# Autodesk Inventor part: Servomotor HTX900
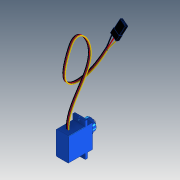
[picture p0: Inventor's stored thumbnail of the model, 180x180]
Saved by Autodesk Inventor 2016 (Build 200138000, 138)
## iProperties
Created: 2016-01
Part Number: Servomotor HTX900
Material: Поликарбонат, дымчатый
Document SubType Name: Modeling
Designer: Evgeny
Density: 1.2 g/cm^3
Appearance: Анодированный — синий
Author: Evgeny
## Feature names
1. Выдавливание1 [Extrusion]
2. Выдавливание2 [Extrusion]
3. Выдавливание3 [Extrusion]
4. Выдавливание4 [Extrusion]
5. Сопряжение1 [Fillet]
6. Выдавливание5 [Extrusion]
7. Выдавливание6 [Extrusion]
8. Сдвиг1
9. Выдавливание7 [Extrusion]
10. Выдавливание8 [Extrusion]
11. Сдвиг2
12. Сопряжение2 [Fillet]
13. Выдавливание9 [Extrusion]
14. Выдавливание10 [Extrusion]
15. Сдвиг3
16. Сдвиг4
17. Выдавливание11 [Extrusion]
## Parameters: d0 = 12 mm, d1 = 23 mm, d2 = 0.5 mm, d3 = 16 mm, d4 = 0, d5 = 12 mm, d6 = 32.5 mm, d7 = 2 mm, d8 = 2 mm, d9 = 1 mm, d10 = 0.5 mm, d11 = 2 mm, d12 = 0, d13 = 27 mm, d14 = 13.5 mm, d15 = 22.5 mm, d16 = 5 mm, d17 = 0, d18 = 12 mm, d19 = 11.5 mm, d20 = 5.25 mm, d21 = 5.5 mm, d22 = 6 mm, d23 = 11.25 mm, d24 = 4 mm, d25 = 0, d26 = 0.25 mm, d27 = 1.5 mm, d28 = 1.5 mm, d29 = 1.5 mm, d30 = 5 mm, d31 = 0.25 mm, d32 = 0.25 mm, d33 = 0, d34 = 4.5 mm, d35 = 1 mm, d36 = 3 mm, d37 = 0, d38 = 1 mm, d39 = 1 mm, d40 = 1 mm, d41 = 2 mm, d42 = 1 mm, d43 = 5 mm, d44 = 0.8 mm, d45 = 0.4 mm, d46 = 0.4 mm, d47 = 0.2 mm, d48 = 0.5 mm, d49 = 0.5 mm, d50 = 0.5 mm, d51 = 0, d52 = 0, d53 = 0, d54 = 0, d55 = 0, d56 = 0, d57 = 0, d58 = 0, d59 = 5 mm, d60 = 8 mm, d61 = 7.5 mm, d62 = 9 mm, d63 = 2.8 mm, d64 = 0, d65 = 1.4 mm, d66 = 1.2 mm, d67 = 0, d68 = 0, d69 = 12 mm, d70 = 3 mm, d71 = 3 mm, d73 = 2 mm, d74 = 1 mm, d75 = 0, d76 = 0, d77 = 0.25 mm, d78 = 5 mm, d79 = 2 mm, d80 = 2 mm, d81 = 2 mm, d82 = 3.5 mm, d83 = 2.2 mm, d84 = 2.2 mm, d85 = 0.25 mm, d86 = 0, d87 = 1.5 mm, d88 = 1.5 mm, d89 = 1.5 mm, d90 = 1.5 mm, d91 = 1.5 mm, d92 = 1.5 mm, d93 = 3 mm, d94 = 2 mm, d95 = 0.5 mm, d96 = 0, d97 = 2 mm, d98 = 1 mm, d99 = 0, d100 = 0, d102 = 1 mm, d103 = 0, d104 = 0, d105 = 1.5 mm, d106 = 2 mm, d107 = 0.25 mm, d108 = 1.5 mm, d109 = 1.5 mm, d110 = 0.25 mm, d111 = 0.25 mm, d112 = 0.25 mm, d113 = 1.5 mm, d114 = 0.05 mm, d115 = 0
